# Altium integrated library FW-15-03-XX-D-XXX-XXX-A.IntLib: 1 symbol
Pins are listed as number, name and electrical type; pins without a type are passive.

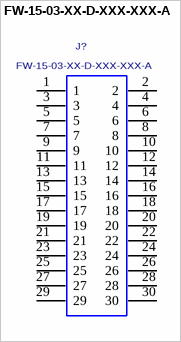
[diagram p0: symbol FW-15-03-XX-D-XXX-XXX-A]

## FW-15-03-XX-D-XXX-XXX-A
designator J?
.050 x .050 SURFACE MOUNT BOARD SPACERS, 30 PINS.; MANUFACTURER: SAMTEC
footprint FW-15-03-XX-D-XXX-XXX-A
pins: 1, 2, 3, 4, 5, 6, 7, 8, 9, 10, 11, 12, 13, 14, 15, 16, 17, 18, 19, 20, 21, 22, 23, 24, 25, 26, 27, 28, 29, 30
